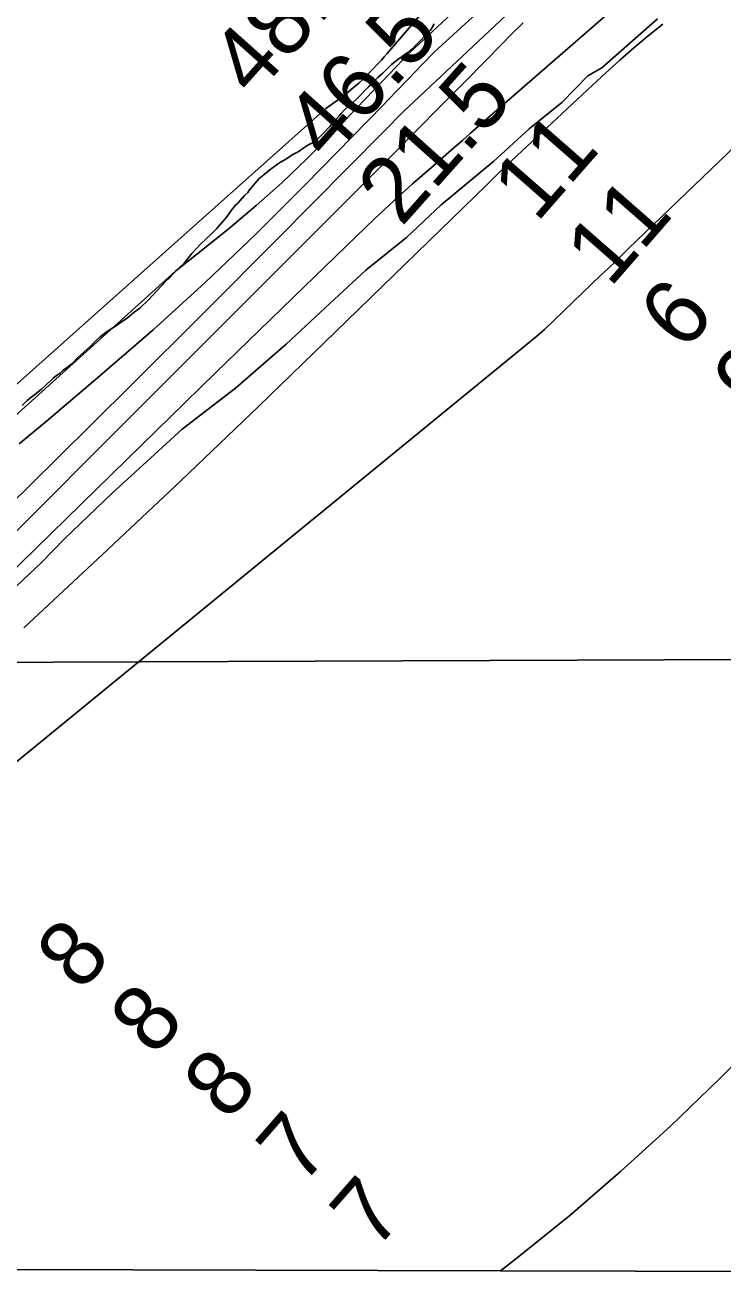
# Model space of a CAD drawing. Extents: x 3172297 to 3210190, y 958463 to 983887.
# Drawn here: x 3193444 to 3194156, y 963866 to 965148 of the extents above; entities that cross this region are included whole.
import ezdxf

# ---------------------------------------------------------------- set-up
doc = ezdxf.new("R2010")
doc.units = 0
for name, color, linetype in [('V-RIVR-EDGE', 7, 'Continuous'), ('V-RIVR-RANG', 7, 'Continuous'), ('V-SITE-VEGE', 7, 'Continuous'), ('V-TOPO-BNDY', 7, 'Continuous'), ('V-TOPO-DPTH', 7, 'Continuous'), ('V-TOPO-MAJR', 7, 'Continuous'), ('V-TOPO-MINR', 7, 'Continuous'), ('V-TOPO-WATR', 7, 'Continuous')]:
    doc.layers.add(name, color=color, linetype=linetype)

msp = doc.modelspace()

# ---------------------------------------------------------------- linework, layer by layer
at = {"layer": 'V-RIVR-EDGE'}
msp.add_lwpolyline([(3194089.7, 965154.1), (3194032.7, 965104.2), (3194018.7, 965096), (3193992, 965068.7), (3193958.6, 965041.8), (3193922.4, 965008.9), (3193868.9, 964964.4), (3193833.3, 964931), (3193791.9, 964897.5), (3193755.2, 964863.5), (3193710.5, 964822.1), (3193658.9, 964777.3), (3193604.2, 964735.4), (3193572, 964705.9), (3193532.7, 964669.9), (3193484.2, 964623.6), (3193460.6, 964599.2), (3193423, 964563.5)], dxfattribs=at)
at = {"layer": 'V-SITE-VEGE'}
for p, q in [((3193845.7, 965130.1), (3193854.3, 965138.8)), ((3193854.3, 965138.8), (3193857.8, 965142.7)), ((3193857.8, 965142.7), (3193859.5, 965145.2)), ((3193859.5, 965145.2), (3193861.6, 965148.9)), ((3193839.5, 965123.6), (3193842.7, 965126.9)), ((3193842.7, 965126.9), (3193845.7, 965130.1)), ((3193818.2, 965107.4), (3193825.9, 965113.6)), ((3193825.9, 965113.6), (3193828.5, 965115.4)), ((3193828.5, 965115.4), (3193830.9, 965117.3)), ((3193830.9, 965117.3), (3193834.3, 965119.5)), ((3193834.3, 965119.5), (3193839.5, 965123.6)), ((3193804.2, 965094.2), (3193809.4, 965099.1)), ((3193809.4, 965099.1), (3193818.2, 965107.4)), ((3193795.4, 965085.5), (3193798, 965087.7)), ((3193798, 965087.7), (3193804.2, 965094.2)), ((3193782.1, 965071.9), (3193795.4, 965085.5)), ((3193766.8, 965057.6), (3193770.2, 965061.3)), ((3193770.2, 965061.3), (3193775.8, 965066.7)), ((3193775.8, 965066.7), (3193778.6, 965068.8)), ((3193778.6, 965068.8), (3193782.1, 965071.9)), ((3193757.3, 965046.6), (3193761.9, 965052.2)), ((3193761.9, 965052.2), (3193764.6, 965055)), ((3193764.6, 965055), (3193766.8, 965057.6)), ((3193742.9, 965031.6), (3193748.1, 965036.6)), ((3193748.1, 965036.6), (3193755, 965044.2)), ((3193755, 965044.2), (3193757.3, 965046.6)), ((3193722.9, 965018.4), (3193728.7, 965022.5)), ((3193728.7, 965022.5), (3193733.7, 965025.8)), ((3193733.7, 965025.8), (3193734.1, 965025.8)), ((3193734.1, 965025.8), (3193737.3, 965027.5)), ((3193737.3, 965027.5), (3193742.9, 965031.6)), ((3193704.8, 965008), (3193710.9, 965011.3)), ((3193710.9, 965011.3), (3193716.7, 965015.2)), ((3193716.7, 965015.2), (3193722.9, 965018.4)), ((3193688.1, 964995.4), (3193695.2, 965001.1)), ((3193695.2, 965001.1), (3193699, 965003.7)), ((3193699, 965003.7), (3193701.6, 965005.8)), ((3193701.6, 965005.8), (3193704.8, 965008)), ((3193673.2, 964979.6), (3193683.1, 964991.1)), ((3193683.1, 964991.1), (3193688.1, 964995.4)), ((3193661, 964966), (3193668.1, 964973.8)), ((3193668.1, 964973.8), (3193671.3, 964977)), ((3193671.3, 964977), (3193673.2, 964979.6)), ((3193650, 964952), (3193654.7, 964958.7)), ((3193654.7, 964958.7), (3193658.8, 964963.8)), ((3193658.8, 964963.8), (3193661, 964966)), ((3193639.3, 964939.8), (3193650, 964952)), ((3193623.1, 964924.3), (3193634.5, 964935.1)), ((3193634.5, 964935.1), (3193639.3, 964939.8)), ((3193614.1, 964914.5), (3193618.8, 964919.9)), ((3193618.8, 964919.9), (3193623.1, 964924.3)), ((3193606.2, 964904.8), (3193614.1, 964914.5)), ((3193590.9, 964889.4), (3193595.9, 964894.6)), ((3193595.9, 964894.6), (3193601.4, 964900)), ((3193601.4, 964900), (3193606.2, 964904.8)), ((3193569.6, 964866.9), (3193587.5, 964886.4)), ((3193587.5, 964886.4), (3193590.9, 964889.4)), ((3193555.4, 964854.8), (3193561, 964858.9)), ((3193561, 964858.9), (3193569.6, 964866.9)), ((3193537.4, 964841.2), (3193539.9, 964843.1)), ((3193539.9, 964843.1), (3193548.5, 964849)), ((3193548.5, 964849), (3193555.4, 964854.8)), ((3193520.6, 964829.7), (3193526.8, 964834.4)), ((3193526.8, 964834.4), (3193529.6, 964836.4)), ((3193529.6, 964836.4), (3193537.4, 964841.2)), ((3193506.8, 964816.5), (3193512.2, 964821.4)), ((3193512.2, 964821.4), (3193517.1, 964826.6)), ((3193517.1, 964826.6), (3193520.6, 964829.7)), ((3193491.8, 964802.2), (3193498, 964808.7)), ((3193498, 964808.7), (3193506.8, 964816.5)), ((3193476.9, 964790.7), (3193479.7, 964792.4)), ((3193479.7, 964792.4), (3193482.7, 964795.7)), ((3193482.7, 964795.7), (3193485.5, 964797.4)), ((3193485.5, 964797.4), (3193489.4, 964800.2)), ((3193489.4, 964800.2), (3193491.8, 964802.2)), ((3193460.6, 964776.2), (3193464.2, 964779.4)), ((3193464.2, 964779.4), (3193473, 964787.9)), ((3193473, 964787.9), (3193476.9, 964790.7)), ((3193445.9, 964764.5), (3193448.3, 964766.7)), ((3193448.3, 964766.7), (3193453.9, 964770.6)), ((3193453.9, 964770.6), (3193460.6, 964776.2)), ((3193441, 964759.5), (3193445.9, 964764.5))]:
    msp.add_line(p, q, dxfattribs=at)
at = {"layer": 'V-TOPO-BNDY'}
msp.add_lwpolyline([(3186048.8, 963896), (3186249.6, 964470), (3198733.3, 964517.6), (3198114.7, 963866.1)], dxfattribs=at)
at = {"layer": 'V-TOPO-DPTH'}
for points in [[(3192733.4, 963879.4), (3192788.4, 963940.6), (3192853.7, 964012.9), (3193199.7, 964394.1), (3193215.4, 964411.2), (3193231.3, 964428.1), (3193247.5, 964444.8), (3193263.9, 964461.3), (3193345.6, 964542.5), (3193403, 964599.6), (3193460.3, 964656.6), (3193517.5, 964713.8), (3193574.7, 964771), (3193820.3, 965016.8), (3193844.1, 965040.7), (3193867.9, 965064.6), (3193891.6, 965088.6), (3193915.3, 965112.6), (3193941.7, 965139.4), (3193952.4, 965149.9)], [(3194095.1, 965148.8), (3194080.2, 965136.7), (3194065.6, 965124.4), (3194051.1, 965111.8), (3194036.9, 965099.1), (3194022.8, 965086.1), (3193956.5, 965024.2), (3193946.1, 965014.3), (3193935.6, 965004.4), (3193925.2, 964994.5), (3193914.9, 964984.4), (3193761, 964834.6), (3193682.1, 964758.4), (3193602.9, 964682.6), (3193523, 964607.4), (3193442.7, 964532.7)], [(3194095.1, 965148.8), (3194080.2, 965136.7), (3194065.6, 965124.4), (3194051.1, 965111.8), (3194036.9, 965099.1), (3194022.8, 965086.1), (3193956.5, 965024.2), (3193946.1, 965014.3), (3193935.6, 965004.4), (3193925.2, 964994.5), (3193914.9, 964984.4), (3193761, 964834.6), (3193682.1, 964758.4), (3193602.9, 964682.6), (3193523, 964607.4), (3193442.7, 964532.7)], [(3192803, 963879.3), (3193929.4, 963876.5), (3193946.5, 963889.6), (3194000, 963932.8), (3194052, 963977.9), (3194102.9, 964024.1), (3194152.4, 964071.8), (3194200.9, 964120.6)], [(3194200.9, 964120.6), (3194152.4, 964071.8), (3194102.9, 964024.1), (3194052, 963977.9), (3194000, 963932.8), (3193946.5, 963889.6), (3193929.4, 963876.5)], [(3193929.4, 963876.5), (3194481.2, 963875.1)]]:
    msp.add_lwpolyline(points, dxfattribs=at)
at = {"layer": 'V-TOPO-MAJR'}
msp.add_lwpolyline([(3194548.5, 965780.8), (3193836.5, 965119.6), (3193829.6, 965112.2), (3193822.6, 965104.8), (3193815.6, 965097.5), (3193808.6, 965090.1), (3193756.4, 965036), (3193731.5, 965011.1), (3193706.1, 964986.8), (3193679.8, 964963.5), (3193652.9, 964940.7), (3193625.4, 964918.7), (3193597.8, 964896.8), (3193188.3, 964527.8), (3193172.2, 964511.1), (3193156.2, 964494.2), (3193140.5, 964477.1), (3193124.9, 964459.9), (3192868.1, 964172.4), (3192789.1, 964083.4), (3192710.4, 963994), (3192632.3, 963904.2), (3192611.2, 963879.7)], dxfattribs=at)
at = {"layer": 'V-TOPO-MINR'}
for points in [[(3194767.1, 965937.8), (3193830.3, 965059.4), (3193810, 965038.9), (3193701.6, 964929.5), (3193626.9, 964854.5), (3193552, 964779.8), (3193476.7, 964705.4), (3193401.1, 964631.2), (3193263.2, 964496.5), (3193237.5, 964470.9), (3193212.1, 964445), (3193187.3, 964418.5), (3193162.8, 964391.8), (3192702.4, 963879.5)], [(3194506.7, 965708.5), (3193861.8, 965120.6), (3193848.8, 965106.9), (3193835.7, 965093.2), (3193822.6, 965079.6), (3193809.4, 965066), (3193730.4, 964985.1), (3193679.6, 964934.5), (3193627.8, 964884.9), (3193574.6, 964836.8), (3193520.4, 964789.8), (3193465.3, 964743.3), (3193437.9, 964720.4)], [(3192571.8, 963879.8), (3193091.5, 964458.1), (3193115.1, 964483.9), (3193138.8, 964509.6), (3193162.8, 964534.9), (3193187.1, 964560.1), (3193751, 965062.6), (3193756.8, 965066.7), (3193762.5, 965070.8), (3193768.2, 965075.1), (3193773.8, 965079.4), (3193779.2, 965083.9), (3193784.6, 965088.5), (3193789.7, 965093.4), (3193794.7, 965098.4), (3193807.8, 965112.1), (3193809.3, 965113.7), (3193810.7, 965115.3), (3193813.7, 965118.6), (3194212, 965582.1)], [(3194086.3, 965200.8), (3193915.1, 965051.7), (3193906.9, 965044.5), (3193898.6, 965037.3), (3193890.4, 965030.1), (3193882.1, 965022.9), (3193859.2, 965002.9), (3193839.6, 964985.6), (3193820.1, 964968), (3193801, 964950.2), (3193782.1, 964932.1), (3193728.8, 964880.5), (3193683.3, 964836.5), (3193638, 964792.4), (3193592.6, 964748.3), (3193547.3, 964704.2), (3193408.1, 964568.3)], [(3194337.3, 965186), (3194060.2, 964919.6), (3194053.2, 964912.9), (3194046.3, 964906.2), (3194039.3, 964899.5), (3194032.3, 964892.8), (3193974.2, 964837), (3193966.6, 964830.2), (3193356.5, 964332), (3193352.6, 964328.4), (3193348.8, 964324.7), (3193345, 964321.1), (3193341.1, 964317.4), (3193310.7, 964288.6), (3193291.6, 964270.7), (3193272.3, 964252.9), (3193252.9, 964235.3), (3193233.3, 964217.9), (3193205.6, 964193.5), (3193172.2, 964163.9), (3193138.9, 964134.1), (3193105.9, 964104), (3193073, 964073.7), (3192863.4, 963879.1)], [(3193952.4, 965149.9), (3193941.7, 965139.4), (3193915.3, 965112.6), (3193891.6, 965088.6), (3193867.9, 965064.6), (3193844.1, 965040.7), (3193820.3, 965016.8), (3193574.7, 964771), (3193517.5, 964713.8), (3193460.3, 964656.6), (3193403, 964599.6), (3193345.6, 964542.5), (3193263.9, 964461.3), (3193247.5, 964444.8), (3193231.3, 964428.1), (3193215.4, 964411.2), (3193199.7, 964394.1), (3192853.7, 964012.9), (3192788.4, 963940.6), (3192733.4, 963879.4)], [(3194200.9, 964120.6), (3194152.4, 964071.8), (3194102.9, 964024.1), (3194052, 963977.9), (3194000, 963932.8), (3193946.5, 963889.6), (3193929.4, 963876.5)]]:
    msp.add_lwpolyline(points, dxfattribs=at)
at = {"layer": 'V-TOPO-WATR'}
msp.add_lwpolyline([(3194095.1, 965148.8), (3194080.2, 965136.7), (3194065.6, 965124.4), (3194051.1, 965111.8), (3194036.9, 965099.1), (3194022.8, 965086.1), (3193956.5, 965024.2), (3193946.1, 965014.3), (3193935.6, 965004.4), (3193925.2, 964994.5), (3193914.9, 964984.4), (3193761, 964834.6), (3193682.1, 964758.4), (3193602.9, 964682.6), (3193523, 964607.4), (3193442.7, 964532.7)], dxfattribs=at)

# ---------------------------------------------------------------- texts
at = {"layer": 'V-RIVR-RANG'}
for s, rotation, p in [('48.6', 48.2483, (3193677.4, 965072.4)), ('46.5', 48.2483, (3193753.4, 965007.4)), ('21.5', 48.2483, (3193828.2, 964941)), ('11', 48.82, (3193966.3, 964945.1)), ('11', 48.82, (3194041.1, 964878.7)), ('6', 48.82, (3194116.7, 964813.3)), ('9', 48.82, (3194191.6, 964747.1)), ('8', 48.7869, (3193500.7, 964159.8)), ('8', 48.7869, (3193575.8, 964093.7)), ('8', 48.7869, (3193650.8, 964027.7)), ('7', 48.7869, (3193726.2, 963962)), ('7', 48.7869, (3193801.3, 963895.9))]:
    msp.add_text(s, height=67, rotation=rotation, dxfattribs=at).set_placement(p)

doc.saveas('drawing.dxf')
